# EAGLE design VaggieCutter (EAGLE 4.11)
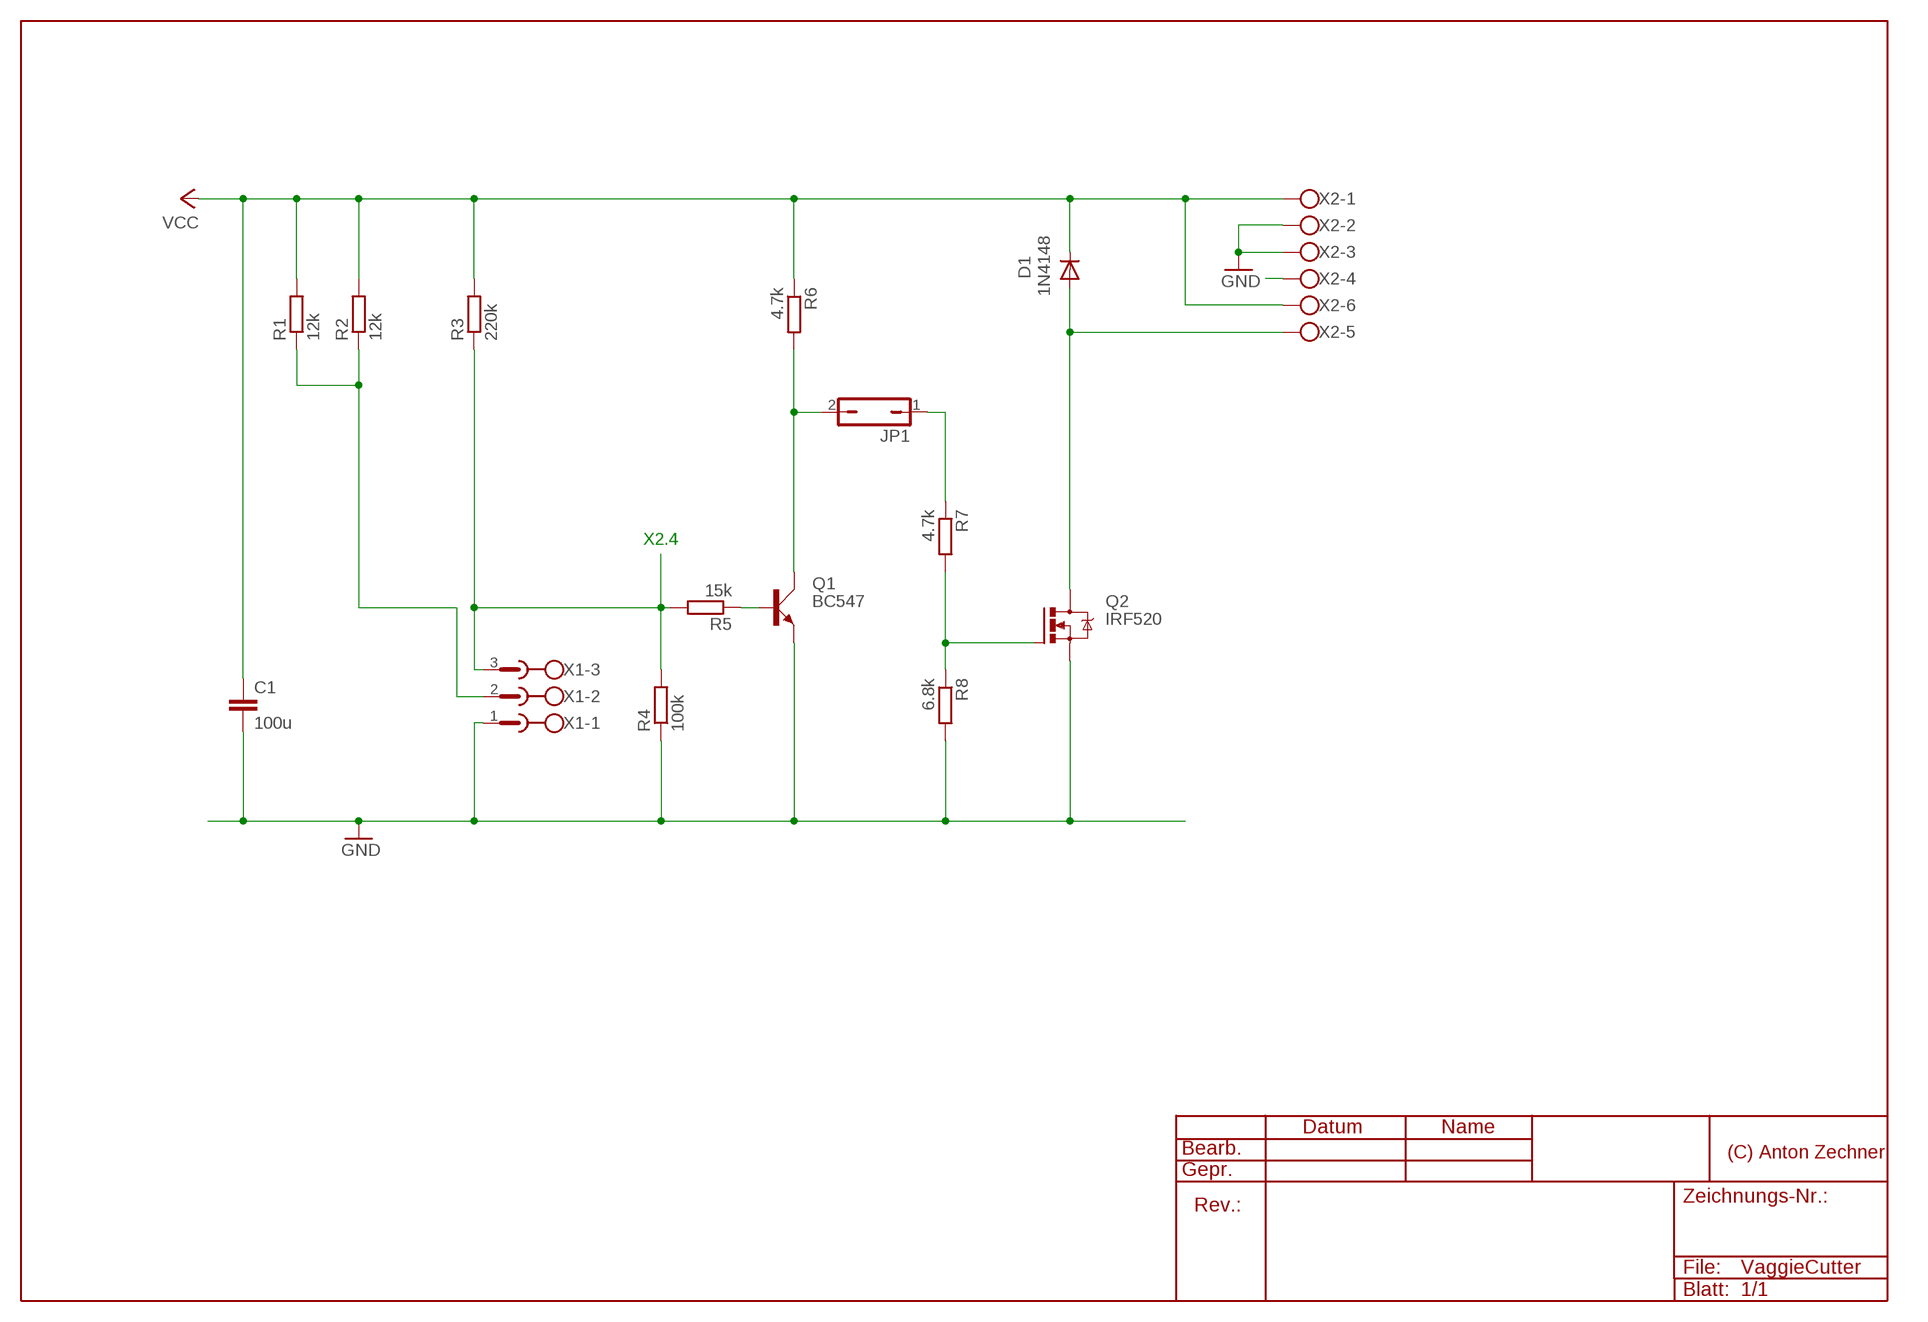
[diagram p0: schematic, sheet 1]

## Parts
C1  100u  C5/3.5  [C5B3.5]
D1  1N4148  [DO35-10]
JP1  JP1QCOMMON  [JP1]
Q1  BC547  [SOT54A]
Q2  IRF520  [TO220BV]
R1  12k  R-EU_0207/10  [0207/10]
R2  12k  R-EU_0207/10  [0207/10]
R3  220k  R-EU_0207/10  [0207/10]
R4  100k  R-EU_0207/10  [0207/10]
R5  15k  R-EU_0207/10  [0207/10]
R6  4.7k  R-EU_0207/10  [0207/10]
R7  4.7k  R-EU_0207/10  [0207/10]
R8  6.8k  R-EU_0207/10  [0207/10]
X1  W232-3  [W232-3]
X2  W237-06P  [W237-6P]

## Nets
BASIS: Q1.B R5.1
EMITTER: JP1.2 Q1.C R6.2
GATE: Q2.G R7.2 R8.1
GND: C1.2 Q1.E Q2.S R4.1 R8.2 X1.1 X2.2 X2.3
MOTOR_OUT: D1.A Q2.D X2.5
OPTO_DIODE: R1.1 R2.1 X1.2
OPTO_ON: R3.1 R4.2 R5.2 X1.3 X2.4
PRE_GATE: JP1.1 R7.1
VCC: C1.1 D1.C R1.2 R2.2 R3.2 R6.1 X2.1 X2.6

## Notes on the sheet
- X2.4

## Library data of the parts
C1 = capacitor-wima:C: CAPACITOR
D1 = AZ-Bauteile:1N4148: DIODE
JP1 = AZ-Bauteile:JP1Q: JUMPER
Q1 = transistor-small-signal:BC547: NPN TRANSISTOR
Q2 = transistor-power:IRF520: HEXFET Power MOSFET
R1-R8 = rcl:R-EU_: RESISTOR, European symbol
X1 = con-wago-508:W232-3: WAGO SREW CLAMP
X2 = con-wago-508:W237-06P: WAGO SREW CLAMP

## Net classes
0 default: width 0.508 mm
1 VCC: width 0.914 mm
2 GND: width 0.914 mm
3 MOTOR_OUT: width 0.914 mm

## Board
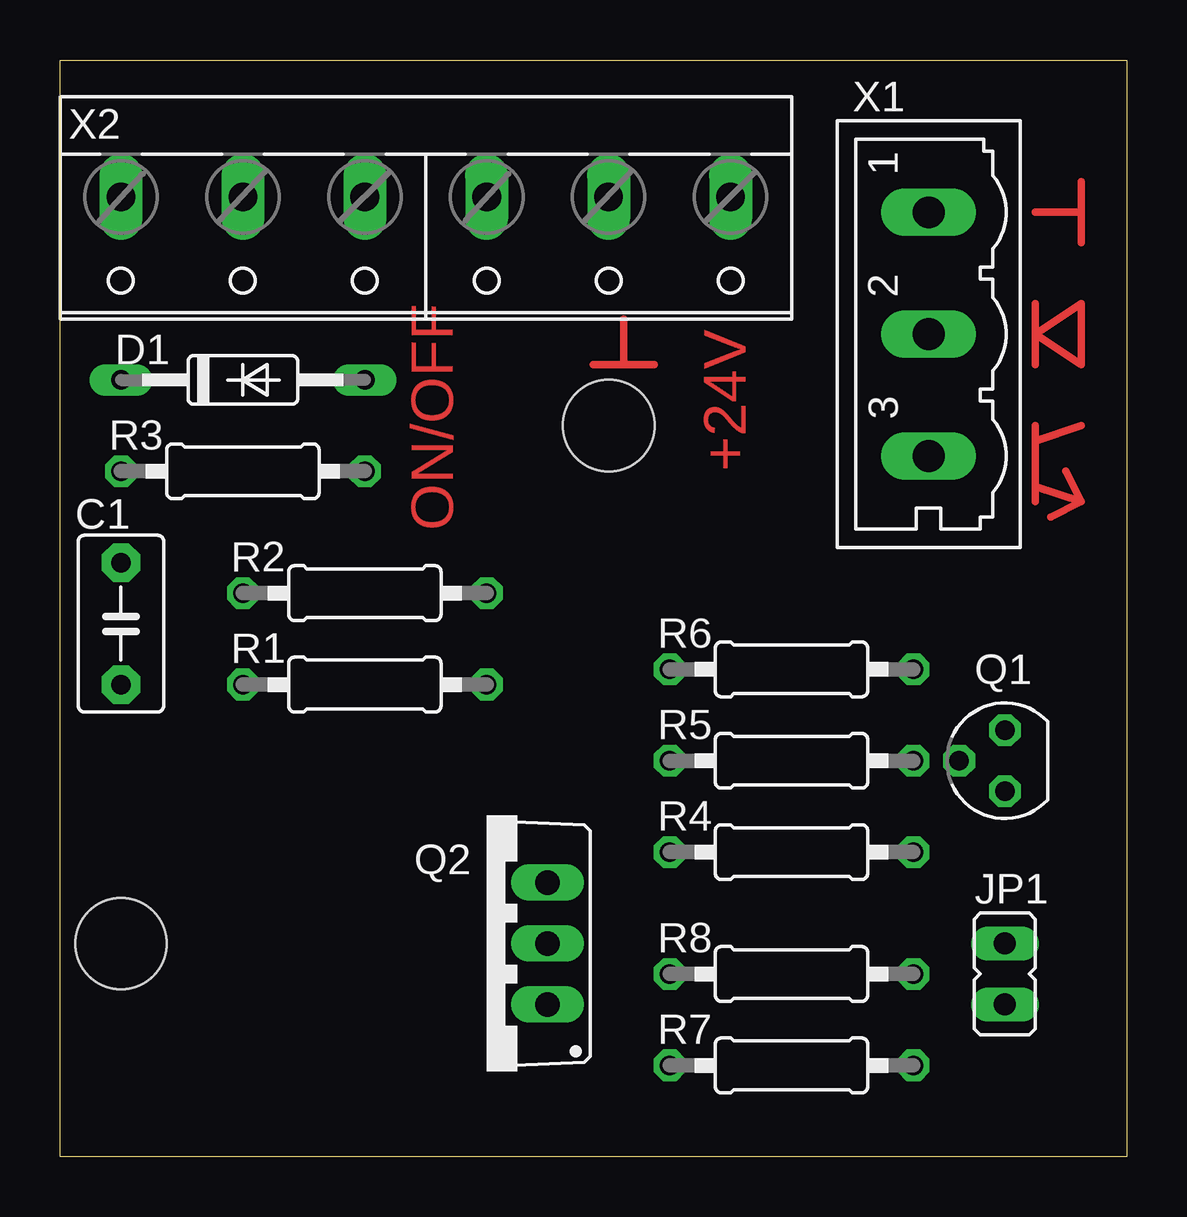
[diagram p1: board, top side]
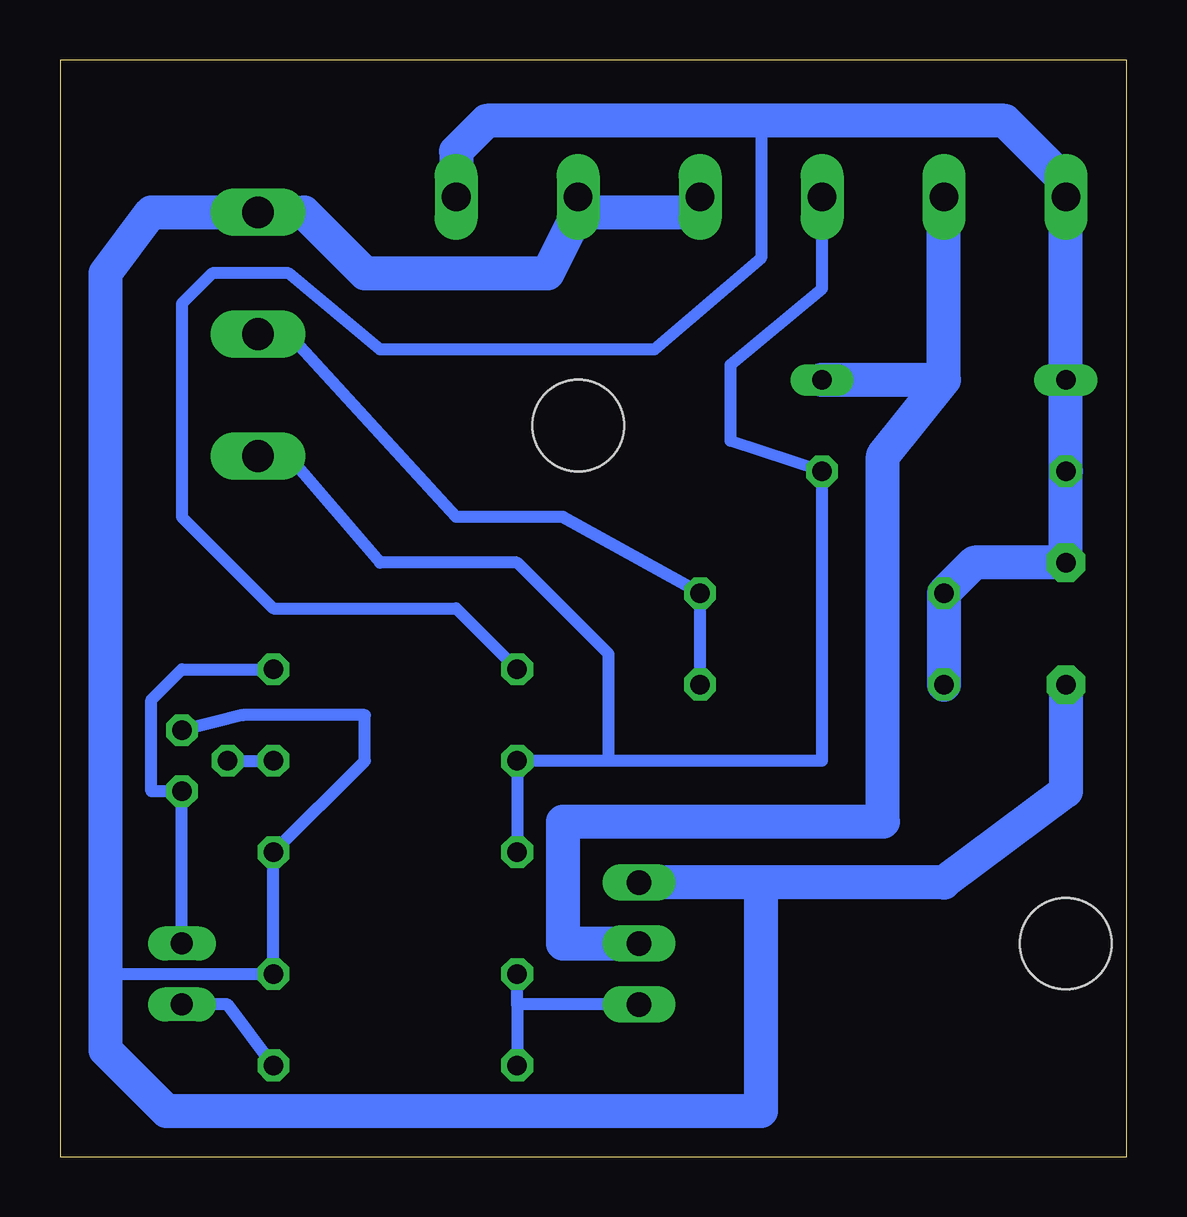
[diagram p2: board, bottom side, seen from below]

Size 44.45 x 45.72 mm. Coordinates in mm from the lower left corner, seen from the top.
Outline: 0,0 0,45.72 44.45,45.72 44.45,0 0,0
Copper layers (1+16): Top 0.035mm / dielectric 1.5mm / Bottom 0.035mm
Design rules "default": minimum track width 10mil, minimum drill 24mil, track to track 8mil, track to pad 8mil, pad to pad 8mil, via to via 8mil, smd to smd 8mil, copper to edge 40mil, drill to drill 8mil, minimum pad ring 10mil, minimum via ring 8mil, stop-mask expansion 4mil, vias tented up to drill 0mil, thermal gap 10mil
Holes 3.81 mm at 22.86,30.48 2.54,8.89

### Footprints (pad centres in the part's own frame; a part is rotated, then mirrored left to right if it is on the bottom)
C5B3.5 = drill 0.813 pad 1.6 octagon: 1 -2.54,0; 2 2.54,0
DO35-10 = drill 0.813 long: A 5.08,0; C -5.08,0
JP1 = drill 0.914 long: 1 0,-1.27; 2 0,1.27
SOT54A = drill 0.813 octagon: B 0,1.905; C -1.27,0; E 1.27,0
TO220BV = drill 1.016 long: D 0,-2.54; G -2.54,-2.54; S 2.54,-2.54
0207/10 = drill 0.813 octagon: 1 -5.08,0; 2 5.08,0
W232-3 = drill 1.321 long: 1 -5.08,-0.635; 2 0,-0.635; 3 5.08,-0.635
W237-6P = drill 1.194 long: 1 -12.7,-0.635; 2 -7.62,-0.635; 3 -2.54,-0.635; 4 2.54,-0.635; 5 7.62,-0.635; 6 12.7,-0.635

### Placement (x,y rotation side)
C1  2.54,22.23 270 top
D1  7.62,32.38 0 top
JP1  39.37,7.62 0 top
Q1  39.37,16.51 90 top
Q2  17.78,8.89 90 top
R1  12.7,19.68 180 top
R2  12.7,23.5 180 top
R3  7.62,28.57 180 top
R4  30.48,12.7 180 top
R5  30.48,16.51 180 top
R6  30.48,20.32 0 top
R7  30.48,3.81 180 top
R8  30.48,7.62 0 top
X1  36.83,34.29 270 top
X2  15.24,39.37 180 top

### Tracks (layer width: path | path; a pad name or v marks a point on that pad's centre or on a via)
BASIS
  Bottom 0.508: Q1.B R5.1
EMITTER
  Bottom 0.508: R6.2 39.37,20.32 40.64,19.05 40.64,15.24 Q1.C JP1.2
GATE
  Bottom 0.508: 25.4,6.35 R8.1 | 25.4,6.35 R7.2 | Q2.G 25.4,6.35
GND
  Bottom 0.508: 34.29,39.37 35.56,39.37 X1.1 | Q1.E 36.83,18.41 31.75,18.41 31.75,16.51 R4.1 R8.2 42.55,7.62
  Bottom 1.422: 22.86,39.37 17.78,39.37 X2.3 | 34.29,39.37 31.75,36.83 24.13,36.83 22.86,39.37 | 22.86,39.37 X2.2 | 35.56,39.37 39.37,39.37 40.64,39.37 42.55,36.83 42.55,7.62 42.55,4.45 40.01,1.91 15.24,1.91 15.24,11.43 | 15.24,11.43 Q2.S | C1.2 2.54,15.24 7.62,11.43 15.24,11.43
MOTOR_OUT
  Bottom 0.508: 7.62,39.37 X2.5
  Bottom 1.422: 7.62,32.38 10.16,29.21 10.16,13.97 23.5,13.97 23.5,8.89 Q2.D | 7.62,32.38 7.62,39.37 | 7.62,32.38 D1.A
N$1
  Top 0.305: 42.55,40.64 42.55,39.37 | 42.55,39.37 42.55,38.1 | 40.64,39.37 42.55,39.37
N$2
  Top 0.305: 40.64,35.56 40.64,34.29 | 40.64,34.29 40.64,33.02 | 40.64,34.29 42.55,35.56 42.55,33.02 40.64,34.29
N$3
  Top 0.305: 40.64,30.48 40.64,29.84 | 40.64,29.84 40.64,27.94 | 40.64,27.94 40.64,27.3 | 40.64,29.84 42.55,30.48 | 40.64,27.94 42.55,27.3 | 42.55,27.3 41.91,28.57 | 42.55,27.3 41.27,26.67
N$4
  Top 0.305: 22.23,33.02 23.5,33.02 | 23.5,33.02 24.77,33.02 | 23.5,33.02 23.5,34.92
OPTO_DIODE
  Bottom 0.508: R1.1 R2.1 23.5,26.67 27.94,26.67 34.92,34.29 X1.2
OPTO_ON
  Bottom 0.508: 21.59,16.51 R5.2 R4.2 | 21.59,16.51 12.7,16.51 R3.1 16.51,29.84 16.51,33.02 12.7,36.2 X2.4 | 21.59,16.51 21.59,20.95 25.4,24.77 31.11,24.77 34.92,29.21 X1.3
PRE_GATE
  Bottom 0.508: R7.1 37.47,6.35 JP1.1
VCC
  Bottom 0.508: R6.1 27.94,22.86 35.56,22.86 39.37,26.67 39.37,35.56 38.1,36.83 34.92,36.83 31.11,33.66 19.68,33.66 15.24,37.47 15.24,43.18 | 2.54,40.64 X2.6
  Bottom 1.422: R1.2 R2.2 6.35,24.77 C1.1 R3.2 D1.C 2.54,40.64 5.08,43.18 15.24,43.18 26.67,43.18 27.94,41.91 X2.1

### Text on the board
Top: ON/OFF | +24V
